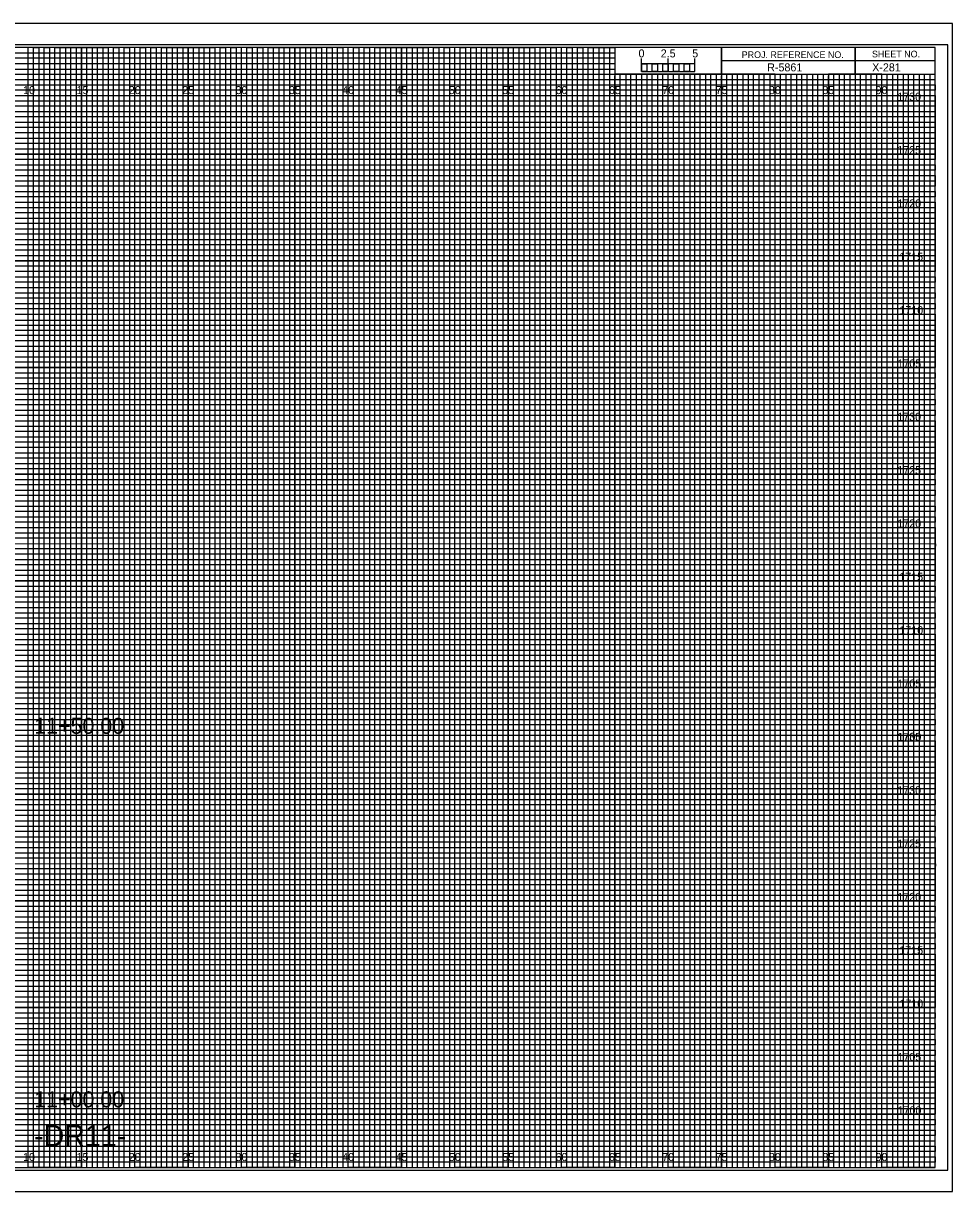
# Model space of a CAD drawing. Extents: x -7 to 162, y -2 to 217.
# Drawn here: x 74.5 to 161.7, y 107.7 to 217.2 of the extents above; entities that cross this region are included whole.
import ezdxf

# ---------------------------------------------------------------- set-up
doc = ezdxf.new("R2010")
doc.units = 0
for name, color, linetype in [('Prop XS Alignment Label', 7, 'Continuous'), ('Prop XS Bar Scale Labels', 7, 'Continuous'), ('Prop XS Elevation Labels', 7, 'Continuous'), ('Prop XS Offset Labels', 7, 'Continuous'), ('Prop XS Project Number', 7, 'Continuous'), ('Prop XS Sheet Number', 7, 'Continuous'), ('Prop XS Station Labels', 7, 'Continuous'), ('Sheet Cross Section CELL', 7, 'Continuous'), ('Sheet Cross Section Grid Major CELL', 7, 'Continuous'), ('Sheet Cross Section Grid Middle CELL', 7, 'Continuous'), ('Sheet Cross Section Grid Minor 1 CELL', 7, 'Continuous'), ('Sheet Cross Section Grid Minor 2 CELL', 7, 'Continuous'), ('Sheet Cross Section Scale CELL', 7, 'Continuous'), ('Sheet Cutting Line CELL', 7, 'Continuous'), ('Sheet DOT Grid CELL', 7, 'Continuous'), ('Sheet Plot Border Inside CELL', 7, 'Continuous'), ('Sheet Plot Border Outside CELL', 7, 'Continuous')]:
    doc.layers.add(name, color=color, linetype=linetype)

msp = doc.modelspace()

# ---------------------------------------------------------------- linework, layer by layer
at = {"layer": 'Sheet Cross Section CELL'}
for p, q in [((152.5, 215), (152.5, 212.5)), ((152.5, 212.5), (152.5, 215)), ((160, 213.75), (140, 213.75)), ((140, 213.75), (140, 212.5)), ((140, 212.5), (160, 212.5))]:
    msp.add_line(p, q, dxfattribs=at)
for points in [[(160, 215), (0, 215), (0, 110), (160, 110)], [(140, 215), (130, 215), (130, 212.52), (140, 212.52)], [(160, 215), (140, 215), (140, 212.5), (160, 212.5)]]:
    msp.add_lwpolyline(points, close=True, dxfattribs=at)
at = {"layer": 'Sheet Cross Section Grid Major CELL'}
for p, q in [((75, 215), (70, 215)), ((75, 110), (75, 215)), ((85, 215), (80, 215)), ((80, 215), (80, 110)), ((85, 110), (85, 215)), ((95, 215), (90, 215)), ((90, 215), (90, 110)), ((95, 110), (95, 215)), ((105, 215), (100, 215)), ((100, 215), (100, 110)), ((105, 110), (105, 215)), ((115, 215), (110, 215)), ((110, 215), (110, 110)), ((115, 110), (115, 215)), ((125, 215), (120, 215)), ((120, 215), (120, 110)), ((125, 110), (125, 215)), ((130, 215), (130, 110)), ((135, 110), (135, 212.5)), ((145, 212.5), (140, 212.5)), ((140, 212.5), (140, 110)), ((145, 110), (145, 212.5)), ((155, 212.5), (150, 212.5)), ((150, 212.5), (150, 110)), ((155, 110), (155, 212.5)), ((80, 110), (75, 110)), ((90, 110), (85, 110)), ((100, 110), (95, 110)), ((110, 110), (105, 110)), ((120, 110), (115, 110)), ((130, 110), (125, 110)), ((140, 110), (135, 110)), ((150, 110), (145, 110)), ((160, 110), (155, 110)), ((160, 110), (160, 110))]:
    msp.add_line(p, q, dxfattribs=at)
for points in [[(0, 210), (160, 210), (160, 205), (0, 205)], [(0, 200), (160, 200), (160, 195), (0, 195)], [(0, 190), (160, 190), (160, 185), (0, 185)], [(0, 180), (160, 180), (160, 175), (0, 175)], [(0, 170), (160, 170), (160, 165), (0, 165)], [(0, 160), (160, 160), (160, 155), (0, 155)], [(0, 150), (160, 150), (160, 145), (0, 145)], [(0, 140), (160, 140), (160, 135), (0, 135)], [(0, 130), (160, 130), (160, 125), (0, 125)], [(0, 120), (160, 120), (160, 115), (0, 115)]]:
    msp.add_lwpolyline(points, dxfattribs=at)
at = {"layer": 'Sheet Cross Section Grid Middle CELL'}
for points in [[(72.5, 110), (77.5, 110), (77.5, 215), (82.5, 215), (82.5, 110), (87.5, 110), (87.5, 215), (92.5, 215), (92.5, 110), (97.5, 110), (97.5, 215), (102.5, 215), (102.5, 110), (107.5, 110), (107.5, 215), (112.5, 215), (112.5, 110), (117.5, 110), (117.5, 215), (122.5, 215), (122.5, 110), (127.5, 110), (127.5, 215), (129.97, 215), (130, 215), (130, 212.5), (132.5, 212.5), (132.5, 110), (137.5, 110), (137.5, 212.5), (142.5, 212.5), (142.5, 110), (147.5, 110), (147.5, 212.5), (152.5, 212.5), (152.5, 110), (157.5, 110), (157.5, 212.5)], [(0, 212.5), (137.5, 212.5)], [(0, 202.5), (160, 202.5), (160, 207.5), (0, 207.5)], [(0, 192.5), (160, 192.5), (160, 197.5), (0, 197.5)], [(0, 182.5), (160, 182.5), (160, 187.5), (0, 187.5)], [(0, 172.5), (160, 172.5), (160, 177.5), (0, 177.5)], [(0, 162.5), (160, 162.5), (160, 167.5), (0, 167.5)], [(0, 152.5), (160, 152.5), (160, 157.5), (0, 157.5)], [(0, 142.5), (160, 142.5), (160, 147.5), (0, 147.5)], [(0, 132.5), (160, 132.5), (160, 137.5), (0, 137.5)], [(0, 122.5), (160, 122.5), (160, 127.5), (0, 127.5)], [(0, 112.5), (160, 112.5), (160, 117.5), (0, 117.5)]]:
    msp.add_lwpolyline(points, dxfattribs=at)
at = {"layer": 'Sheet Cross Section Grid Minor 1 CELL'}
for p, q in [((0, 214.5), (130, 214.5)), ((130, 213.99), (0, 213.99)), ((130, 214.5), (130, 213.99)), ((0, 213.5), (130, 213.5)), ((130, 212.94), (0, 212.94)), ((130, 213.5), (130, 212.94)), ((0, 212), (160, 212))]:
    msp.add_line(p, q, dxfattribs=at)
for points in [[(0, 211.5), (135, 211.5), (160, 211.5), (160, 211), (0, 211)], [(0, 210.5), (160, 210.5), (160, 209.5), (0, 209.5)], [(0, 209), (160, 209), (160, 208.5), (0, 208.49)], [(0, 208), (160, 208), (160, 207), (0, 207)], [(0, 206.5), (160, 206.5), (160, 206), (0, 206)], [(0, 205.5), (160, 205.5), (160, 204.5), (0, 204.5)], [(0, 204), (160, 204), (160, 203.5), (0, 203.5)], [(0, 203), (160, 203), (160, 202), (0, 202)], [(0, 201.5), (160, 201.5), (160, 201), (0, 201)], [(0, 200.5), (160, 200.5), (160, 199.5), (0, 199.5)], [(0, 199), (160, 199), (160, 198.5), (0, 198.5)], [(0, 198), (160, 198), (160, 196.97), (160, 196.5), (160, 196), (0, 196)], [(0, 197), (160, 197), (160, 196.5), (0, 196.5)], [(0, 195.5), (160, 195.5), (160, 194.5), (0, 194.52)], [(0, 194.52), (160, 194.5), (160, 194), (0, 194)], [(0, 193.5), (160, 193.5), (160, 193), (0, 193)], [(0, 192), (160, 192), (160, 191.5), (0, 191.5)], [(0, 191), (160, 191), (160, 190.5), (0, 190.5)], [(-0.04, 189.44), (160, 189.44), (160, 188.94), (-0.04, 188.94)], [(0, 188.5), (160, 188.5), (160, 188), (0, 188)], [(0, 187), (160, 187), (160, 186.5), (0, 186.5)], [(0, 186), (160, 186), (160, 185.5), (0, 185.5)], [(0, 184.5), (160, 184.5), (160, 184), (0, 184)], [(0, 183.5), (160, 183.5), (160, 183), (0, 183)], [(0, 182), (160, 182), (160, 181.5), (0, 181.5)], [(0, 181), (160, 181), (160, 180.5), (0, 180.5)], [(0, 179.5), (160, 179.5), (160, 178.99), (0, 179)], [(0, 178.5), (160, 178.5), (160, 178), (0, 178)], [(0, 177), (160, 177), (160, 176.5), (0, 176.5)], [(0, 176), (160, 176), (160, 175.5), (0, 175.5)], [(0, 174.5), (160, 174.5), (160, 174), (0, 174)], [(0, 173.5), (160, 173.5), (160, 173), (0, 173)], [(0, 172), (160, 172), (160, 171.5), (0, 171.5)], [(0, 171), (160, 171), (160, 170.5), (0, 170.5)], [(0, 169.5), (160, 169.5), (160, 169), (0, 169)], [(0, 168.5), (160.03, 168.46), (160, 168), (0, 168)], [(0, 167), (160, 167), (160, 166.5), (0, 166.5)], [(0, 166), (160, 166), (160, 165.5), (0, 165.5)], [(0, 164.5), (160, 164.5), (160, 164), (0, 164)], [(0, 163.5), (160, 163.5), (160, 163), (0, 163)], [(0, 162), (160, 162), (160, 161.5), (0, 161.5)], [(0, 161), (160, 161), (160, 160.5), (0, 160.5)], [(0, 159.5), (160, 159.5), (160, 159), (0, 159)], [(0, 158.5), (160, 158.5), (160, 158), (0, 158)], [(0, 157), (160, 157), (160, 156.5), (0, 156.5)], [(0, 156), (160, 156), (160, 155.5), (0, 155.5)], [(0, 154.5), (160, 154.5), (160, 154), (0, 154)], [(0, 153.5), (160, 153.5), (160, 153), (0, 153)], [(0, 152), (160, 152), (160, 151.5), (0, 151.5)], [(0, 151), (160, 151), (160, 150.5), (0, 150.5)], [(0, 149.5), (160, 149.5), (160, 148.99), (0, 149)], [(0, 148.5), (160, 148.5), (160, 148), (0, 148)], [(0, 147), (160, 147), (160, 146.5), (0, 146.5)], [(0, 146), (160, 146), (160, 145.5), (0, 145.5)], [(0, 144.5), (160, 144.5), (160, 144), (0, 144)], [(0, 143.5), (160, 143.5), (160, 143), (0, 143)], [(0, 142), (160, 142), (160, 141.5), (0, 141.5)], [(0, 141), (160, 141), (160, 140.5), (0, 140.5)], [(0, 139.5), (160, 139.5), (160, 139), (0, 139)], [(0, 138.5), (160.03, 138.46), (160, 138), (0, 138)], [(0, 137), (160, 137), (160, 136.5), (0, 136.5)], [(0, 136), (160, 136), (160, 135.5), (0, 135.5)], [(0, 134.5), (160, 134.5), (160, 134), (0, 134)], [(0, 133.5), (160, 133.5), (160, 133), (0, 133)], [(0, 132), (160, 132), (160, 131.5), (0, 131.5)], [(0, 131), (160, 131), (160, 130.5), (0, 130.5)], [(0, 129.5), (160, 129.5), (160, 129), (0, 129)], [(0, 128.5), (160, 128.5), (160, 128), (0, 128)], [(0, 127), (160, 127), (160, 126.5), (0, 126.5)], [(0, 126), (160, 126), (160, 125.5), (0, 125.5)], [(0, 124.5), (160, 124.5), (160, 124), (0, 124)], [(0, 123.5), (160, 123.5), (160, 123), (0, 123)], [(0, 122), (160, 122), (160, 121.5), (0, 121.5)], [(0, 121), (160, 121), (160, 120.5), (0, 120.5)], [(0, 119.5), (160, 119.5), (160, 119), (0, 119)], [(0, 118.5), (160, 118.5), (160, 118), (0, 118)], [(0, 117), (160, 117), (160, 116.5), (0, 116.5)], [(0, 116), (160, 116), (160, 115.5), (0, 115.5)], [(0, 114.5), (160, 114.5), (160, 114), (0, 114)], [(0, 113.5), (160, 113.5), (160, 113), (0, 113)], [(0, 112), (160, 112), (160, 111.5), (0, 111.5)], [(0, 111), (160, 111), (160, 110.5), (0, 110.5)]]:
    msp.add_lwpolyline(points, dxfattribs=at)
at = {"layer": 'Sheet Cross Section Grid Minor 2 CELL'}
for p, q in [((133.5, 212.5), (133, 212.5)), ((133, 212.5), (133, 110)), ((133.5, 110), (133.5, 212.5)), ((134.5, 212.5), (134, 212.5)), ((134, 212.5), (134, 110)), ((134.5, 110), (134.5, 212.5)), ((133, 110), (132.5, 110)), ((134, 110), (133.5, 110))]:
    msp.add_line(p, q, dxfattribs=at)
for points in [[(75, 110), (75.5, 110), (75.5, 215), (76, 215), (76, 110)], [(76, 110), (76.5, 110), (76.5, 215), (77, 215), (77, 110)], [(77.5, 110), (78, 110), (78, 215), (78.5, 215), (78.5, 110)], [(78.5, 110), (79, 110), (79, 215), (79.5, 215), (79.5, 110)], [(80, 110), (80.5, 110), (80.5, 215), (81, 215), (81, 110)], [(81, 110), (81.5, 110), (81.5, 215), (82, 215), (82, 110)], [(82.5, 110), (83, 110), (83, 215), (83.5, 215), (83.5, 110)], [(83.5, 110), (84, 110), (84, 215), (84.5, 215), (84.5, 110)], [(85, 110), (85.5, 110), (85.5, 215), (86, 215), (86, 110)], [(86, 110), (86.5, 110), (86.5, 215), (87, 215), (87, 110)], [(87.5, 110), (88, 110), (88, 215), (88.5, 215), (88.5, 110)], [(88.5, 110), (89, 110), (89, 215), (89.5, 215), (89.5, 110)], [(90, 110), (90.5, 110), (90.5, 215), (91, 215), (91, 110)], [(91, 110), (91.5, 110), (91.5, 215), (92, 215), (92, 110)], [(92.5, 110), (93, 110), (93, 215), (93.5, 215), (93.5, 110)], [(93.5, 110), (94, 110), (94, 215), (94.5, 215), (94.5, 110)], [(95, 110), (95.5, 110), (95.5, 215), (96, 215), (96, 110)], [(96, 110), (96.5, 110), (96.5, 215), (97, 215), (97, 110)], [(97.5, 110), (98, 110), (98, 215), (98.5, 215), (98.5, 110)], [(98.5, 110), (99, 110), (99, 215), (99.5, 215), (99.5, 110)], [(100, 110), (100.5, 110), (100.5, 215), (101, 215), (101, 110)], [(101, 110), (101.5, 110), (101.5, 215), (102, 215), (102, 110)], [(102.5, 110), (103, 110), (103, 215), (103.5, 215), (103.5, 110)], [(103.5, 110), (104, 110), (104, 215), (104.5, 215), (104.5, 110)], [(105, 110), (105.5, 110), (105.5, 215), (106, 215), (106, 110)], [(106, 110), (106.5, 110), (106.5, 215), (107, 215), (107, 110)], [(107.5, 110), (108, 110), (108, 215), (108.5, 215), (108.5, 110)], [(108.5, 110), (109, 110), (109, 215), (109.5, 215), (109.5, 110)], [(110, 110), (110.5, 110), (110.5, 215), (111, 215), (111, 110)], [(111, 110), (111.5, 110), (111.5, 215), (112, 215), (112, 110)], [(112.5, 110), (113, 110), (113, 215), (113.5, 215), (113.5, 110)], [(113.5, 110), (114, 110), (114, 215), (114.5, 215), (114.5, 110)], [(115, 110), (115.5, 110), (115.5, 215), (116, 215), (116, 110)], [(116, 110), (116.5, 110), (116.5, 215), (117, 215), (117, 110)], [(117.5, 110), (118, 110), (118, 215), (118.5, 215), (118.5, 110)], [(118.5, 110), (119, 110), (119, 215), (119.5, 215), (119.5, 110)], [(120, 110), (120.5, 110), (120.5, 215), (121, 215), (121, 110)], [(121, 110), (121.5, 110), (121.5, 215), (122, 215), (122, 110)], [(122.5, 110), (123, 110), (123, 215), (123.5, 215), (123.5, 110)], [(123.5, 110), (124, 110), (124, 215), (124.5, 215), (124.5, 110)], [(125, 110), (125.5, 110), (125.5, 215), (126, 215), (126, 110)], [(126, 110), (126.5, 110), (126.5, 215), (127, 215), (127, 110)], [(127.5, 110), (128, 110), (128, 215), (128.5, 215), (128.5, 110)], [(128.5, 110), (129, 110), (129, 215), (129.5, 215), (129.5, 110)], [(130, 110), (130.5, 110), (130.5, 212.5), (131.01, 212.5), (131.01, 110)], [(131, 110), (131.5, 110), (131.5, 212.5), (132, 212.5), (132, 110)], [(135, 110), (135.49, 110), (135.49, 212.5), (136, 212.5), (136, 110)], [(136, 110), (136.5, 110), (136.5, 212.5), (137.03, 212.5), (137.03, 110)], [(137.5, 110), (138, 110), (138, 212.5), (138.5, 212.5), (138.5, 110)], [(138.5, 110), (139, 110), (139, 212.5), (139.5, 212.5), (139.5, 110)], [(140, 110), (140.5, 110), (140.5, 212.5), (141, 212.5), (141, 110)], [(141, 110), (141.5, 110), (141.5, 212.5), (142, 212.5), (142, 110)], [(142.5, 110), (143, 110), (143, 212.5), (143.5, 212.5), (143.5, 110)], [(143.5, 110), (144, 110), (144, 212.5), (144.5, 212.5), (144.5, 110)], [(145, 110), (145.5, 110), (145.5, 212.5), (146, 212.5), (146, 110)], [(146, 110), (146.5, 110), (146.5, 212.5), (147, 212.5), (147, 110)], [(147.5, 110), (148, 110), (148, 212.5), (148.5, 212.5), (148.5, 110)], [(148.5, 110), (149, 110), (149, 212.5), (149.5, 212.5), (149.5, 110)], [(150, 110), (150.5, 110), (150.5, 212.5), (151, 212.5), (151, 110)], [(151, 110), (151.5, 110), (151.5, 212.5), (152, 212.5), (152, 110)], [(152.5, 110), (153, 110), (153, 212.5), (153.5, 212.5), (153.5, 110)], [(153.5, 110), (154, 110), (154, 212.5), (154.5, 212.5), (154.5, 110)], [(155, 110), (155.5, 110), (155.5, 212.5), (156, 212.5), (156, 110)], [(156, 110), (156.5, 110), (156.5, 212.5), (157, 212.5), (157, 110)], [(157.5, 110), (158, 110), (158, 212.5), (158.5, 212.5), (158.5, 110)], [(158.5, 110), (159, 110), (159, 212.5), (159.5, 212.5), (159.5, 110)]]:
    msp.add_lwpolyline(points, dxfattribs=at)
at = {"layer": 'Sheet Cross Section Scale CELL'}
for p, q in [((132.5, 212.75), (132.5, 213.95)), ((132.5, 213.45), (132.5, 213.95)), ((135, 212.75), (135, 213.95)), ((137.5, 212.75), (137.5, 213.95)), ((137.5, 213.45), (137.5, 213.95))]:
    msp.add_line(p, q, dxfattribs=at)
for points in [[(137.5, 213.45), (132.5, 213.45), (132.5, 212.75), (137.5, 212.75)], [(132.5, 213.45), (133, 213.45), (133, 212.75), (132.5, 212.75)], [(133.5, 213.45), (134, 213.45), (134, 212.75), (133.5, 212.75)], [(134.5, 213.45), (135, 213.45), (135, 212.75), (134.5, 212.75)], [(135.5, 213.45), (136, 213.45), (136, 212.75), (135.5, 212.75)], [(136.5, 213.45), (137, 213.45), (137, 212.75), (136.5, 212.75)]]:
    msp.add_lwpolyline(points, close=True, dxfattribs=at)
at = {"layer": 'Sheet Cutting Line CELL'}
for p, q in [((161.65, 217.25), (-6.7, 217.25)), ((-6.7, 107.75), (161.65, 107.75))]:
    msp.add_line(p, q, dxfattribs=at)
at = {"layer": 'Sheet DOT Grid CELL'}
for p, q in [((75, 110), (75, 215)), ((80, 110), (80, 215)), ((85, 110), (85, 215)), ((90, 110), (90, 215)), ((95, 110), (95, 215)), ((100, 110), (100, 215)), ((105, 110), (105, 215)), ((110, 110), (110, 215)), ((115, 110), (115, 215)), ((120, 110), (120, 215)), ((125, 110), (125, 215)), ((130, 110), (130, 212.34)), ((135, 110), (135, 212.34)), ((140, 110), (140, 212.34)), ((145, 110), (145, 212.34)), ((150, 110), (150, 212.34)), ((155, 110), (155, 212.34)), ((0, 210), (160, 210)), ((0, 205), (160, 205)), ((0, 200), (160, 200)), ((0, 195), (160, 195)), ((0, 190), (160, 190)), ((0, 185), (160, 185)), ((0, 180), (160, 180)), ((0, 175), (160, 175)), ((0, 170), (160, 170)), ((0, 165), (160, 165)), ((0, 160), (160, 160)), ((0, 155), (160, 155)), ((0, 150), (160, 150)), ((0, 145), (160, 145)), ((0, 140), (160, 140)), ((0, 135), (160, 135)), ((0, 130), (160, 130)), ((0, 125), (160, 125)), ((0, 120), (160, 120)), ((0, 115), (160, 115))]:
    msp.add_line(p, q, dxfattribs=at)
at = {"layer": 'Sheet Plot Border Inside CELL'}
msp.add_lwpolyline([(-5.4, 109.75), (161.2, 109.75), (161.2, 215.25), (-5.4, 215.25)], close=True, dxfattribs=at)
at = {"layer": 'Sheet Plot Border Outside CELL'}
msp.add_lwpolyline([(-6.7, 107.75), (161.65, 107.75), (161.65, 217.25), (-6.7, 217.25)], close=True, dxfattribs=at)

# ---------------------------------------------------------------- texts
at = {"layer": 'Prop XS Alignment Label'}
msp.add_text('-DR11-', height=2, dxfattribs=at).set_placement((75.56, 112))
at = {"layer": 'Prop XS Bar Scale Labels'}
for s, p in [('2.5', (134.29, 214.06)), ('5', (137.24, 214.06))]:
    msp.add_text(s, height=0.75, dxfattribs=at).set_placement(p)
at = {"layer": 'Prop XS Elevation Labels'}
for s, p in [('1730', (156.46, 210)), ('1725', (156.46, 205)), ('1720', (156.47, 200)), ('1715', (156.65, 195)), ('1710', (156.66, 190)), ('1705', (156.48, 185)), ('1730', (156.46, 180)), ('1725', (156.46, 175)), ('1720', (156.47, 170)), ('1715', (156.65, 165)), ('1710', (156.66, 160)), ('1705', (156.48, 155)), ('1735', (156.45, 150)), ('1700', (156.49, 150)), ('1730', (156.46, 145)), ('1725', (156.46, 140)), ('1720', (156.47, 135)), ('1715', (156.65, 130)), ('1710', (156.66, 125)), ('1705', (156.48, 120)), ('1700', (156.49, 115))]:
    msp.add_text(s, height=0.75, dxfattribs=at).set_placement(p)
at = {"layer": 'Prop XS Offset Labels'}
for s, p in [('10', (74.52, 210.62)), ('15', (79.53, 210.62)), ('20', (84.43, 210.62)), ('25', (89.44, 210.62)), ('30', (94.43, 210.62)), ('35', (99.44, 210.62)), ('40', (104.43, 210.62)), ('45', (109.44, 210.62)), ('50', (114.43, 210.62)), ('55', (119.44, 210.62)), ('60', (124.43, 210.62)), ('65', (129.44, 210.62)), ('70', (134.43, 210.62)), ('75', (139.44, 210.62)), ('80', (144.43, 210.62)), ('85', (149.44, 210.62)), ('90', (154.43, 210.62)), ('10', (74.52, 110.62)), ('15', (79.53, 110.62)), ('20', (84.43, 110.62)), ('25', (89.44, 110.62)), ('30', (94.43, 110.62)), ('35', (99.44, 110.62)), ('40', (104.43, 110.62)), ('45', (109.44, 110.62)), ('50', (114.43, 110.62)), ('55', (119.44, 110.62)), ('60', (124.43, 110.62)), ('65', (129.44, 110.62)), ('70', (134.43, 110.62)), ('75', (139.44, 110.62)), ('80', (144.43, 110.62)), ('85', (149.44, 110.62)), ('90', (154.43, 110.62))]:
    msp.add_text(s, height=0.75, dxfattribs=at).set_placement(p)
at = {"layer": 'Prop XS Project Number'}
msp.add_text('R-5861', height=0.75, dxfattribs=at).set_placement((144.27, 212.75))
at = {"layer": 'Prop XS Sheet Number'}
msp.add_text('X-281', height=0.75, dxfattribs=at).set_placement((154.11, 212.75))
at = {"layer": 'Prop XS Station Labels'}
for s, p in [('11+50.00', (75.57, 150.66)), ('11+00.00', (75.57, 115.65))]:
    msp.add_text(s, height=1.5, dxfattribs=at).set_placement(p)
at = {"layer": 'Sheet Cross Section CELL'}
for s, p in [('PROJ. REFERENCE NO.', (141.88, 214)), ('SHEET NO.', (154.09, 214.06))]:
    msp.add_text(s, height=0.625, dxfattribs=at).set_placement(p)
at = {"layer": 'Sheet Cross Section Scale CELL'}
msp.add_text('0', height=0.75, dxfattribs=at).set_placement((132.21, 214.06))

doc.saveas('drawing.dxf')
